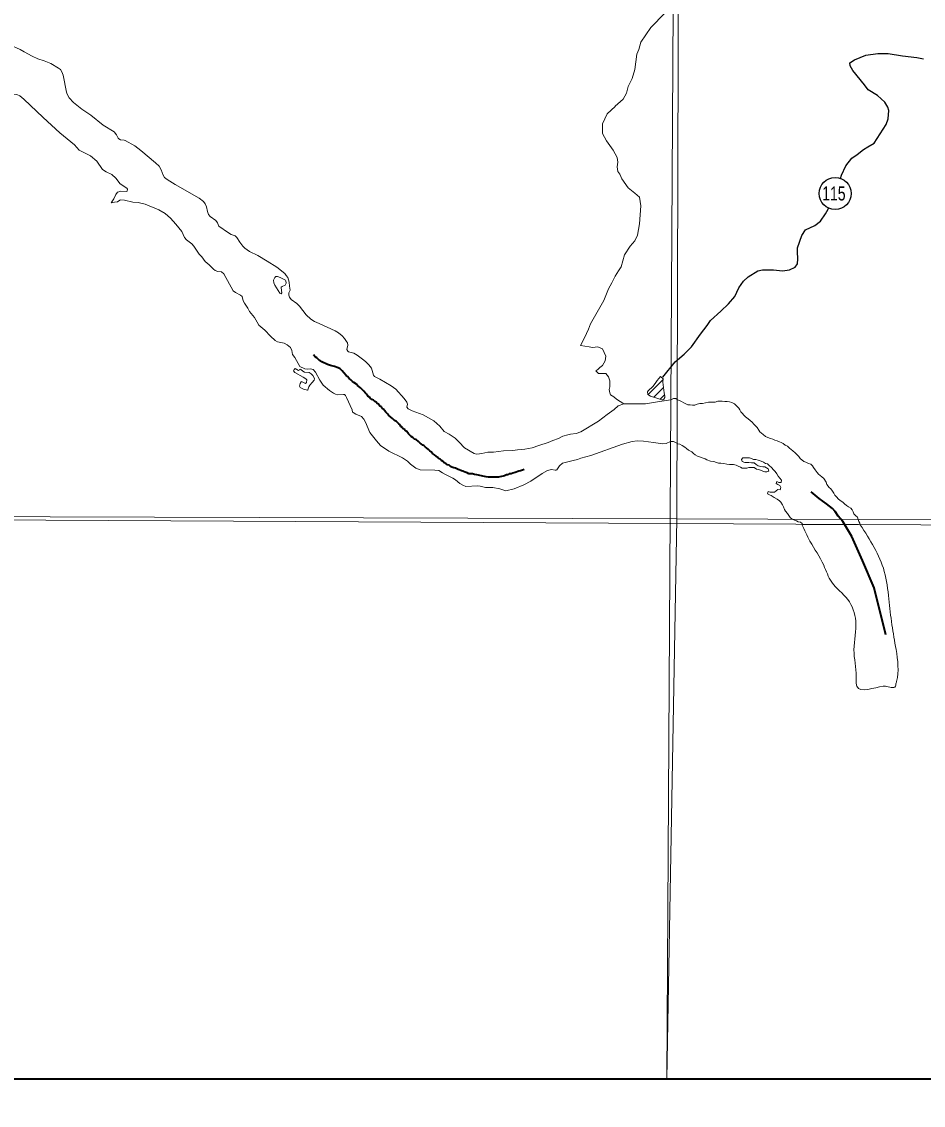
# Model space of a CAD drawing. Extents: x -1643653 to 4543381, y 1624270 to 13878484.
# Drawn here: x 604258 to 608778, y 8895895 to 8901328 of the extents above; entities that cross this region are included whole.
import ezdxf
from ezdxf.enums import TextEntityAlignment as Align

# ---------------------------------------------------------------- set-up
doc = ezdxf.new("R2010")
doc.units = 0
doc.header["$LTSCALE"] = 200
doc.linetypes.add('LONG_DASH_SHORT_DASH', pattern=[9.9, 6, -1.2, 1.5, -1.2])
doc.layers.add('6', color=7, linetype='Continuous', lineweight=13)
doc.layers.add('60', color=7, linetype='Continuous', lineweight=13)

msp = doc.modelspace()

# ---------------------------------------------------------------- linework, layer by layer
at = {"layer": '6'}
for p, q in [((607398.2, 8899458.9), (607473.3, 8899534)), ((607427.1, 8899445.4), (607476, 8899494.2)), ((607458.9, 8899434.7), (607481.1, 8899456.9)), ((608462.4, 8898805.8), (608169.4, 8898807.8))]:
    msp.add_line(p, q, dxfattribs=at)
at = {"layer": '6', "lineweight": 35}
msp.add_lwpolyline([(574695.3, 8924769.6), (626625.7, 8924769.6), (626625.7, 8896026.7), (574695.3, 8896026.7)], close=True, dxfattribs=at)
at = {"layer": '6'}
for points in [[(607657.7, 8924743.3), (607574.2, 8909874.9), (607492.3, 8896026.7)], [(607518.6, 8901403.9), (607482.1, 8901370.7), (607412.3, 8901297.6), (607362.4, 8901224.5), (607352.5, 8901188), (607342.5, 8901164.7), (607332.5, 8901088.4), (607319.2, 8901041.9), (607299.3, 8901002), (607289.3, 8900968.8), (607272.7, 8900938.9), (607233.9, 8900903.3)], [(603607.9, 8901202.5), (603628.6, 8901215.9), (603671.7, 8901230.7), (603774.9, 8901247.2), (603862.9, 8901251.2), (603892.8, 8901248.7), (603993.8, 8901227), (604022.6, 8901225.8), (604073.7, 8901229.1), (604097.1, 8901225.2), (604136.5, 8901210.6), (604149.3, 8901209.6), (604198.3, 8901211), (604250.4, 8901188.4), (604270.6, 8901176.9)], [(604270.6, 8901176.9), (604309.9, 8901154.5), (604339.3, 8901141.9), (604370.9, 8901131.4)], [(604370.9, 8901131.4), (604370.9, 8901131.4), (604403.6, 8901117.1), (604442.5, 8901095.2), (604452, 8901087.1), (604458.6, 8901076.9), (604465.4, 8901060), (604482, 8900973.9), (604485.2, 8900964.1), (604495.8, 8900945.5), (604517.3, 8900922.7), (604558.5, 8900888.9), (604603.8, 8900858.4), (604667, 8900809.4), (604720.7, 8900774.8), (604733.1, 8900760.8), (604741.5, 8900744.4), (604745.2, 8900740.3), (604753.2, 8900735.9), (604770.9, 8900734.2), (604776.8, 8900732.2), (604824.3, 8900704.6), (604854.7, 8900681.5), (604929.1, 8900620.1), (604947.7, 8900602.6), (604957.6, 8900585), (604966.3, 8900557.4), (604974.2, 8900547), (604987.4, 8900535.9), (605027.8, 8900510.6), (605147.2, 8900442.4), (605169.2, 8900426.4), (605178, 8900414.5), (605184.6, 8900400), (605189.5, 8900375.3), (605194.2, 8900361.7), (605203.3, 8900351.7), (605231.7, 8900331.2), (605239.8, 8900319.8), (605246.1, 8900303.3), (605294.8, 8900269.1), (605308.7, 8900261.3), (605318.4, 8900257.2)], [(604366, 8900847), (604269.1, 8900939.9), (604248, 8900956), (604232.7, 8900962.7), (604218.8, 8900964.1), (604182.6, 8900956.3), (604161.8, 8900955.6), (604125.6, 8900973.4), (604104.3, 8900978.3), (604083.2, 8900978.5), (604062.8, 8900972.3)], [(607232.8, 8900902.4), (607193, 8900865.8), (607169.7, 8900816), (607169.7, 8900766.2), (607189.6, 8900729.7), (607222.9, 8900683.2), (607242.8, 8900646.7), (607246.1, 8900623.4), (607242.8, 8900600.2), (607246.1, 8900576.9), (607256.1, 8900563.6), (607266.1, 8900540.4), (607299.3, 8900493.9), (607332.5, 8900467.3), (607355.8, 8900447.4), (607362.4, 8900404.2), (607355.8, 8900314.6), (607345.8, 8900258.1), (607332.5, 8900228.2), (607309.3, 8900201.6), (607279.4, 8900158.5), (607262.7, 8900098.7), (607249.5, 8900078.8), (607232.8, 8900052.2), (607216.2, 8900019), (607199.6, 8899989.1), (607176.3, 8899929.3), (607109.9, 8899813.1), (607099.9, 8899786.5), (607080, 8899743.3), (607060, 8899703.5), (607103.2, 8899696.8), (607119.8, 8899693.5), (607146.4, 8899696.8), (607169.7, 8899686.9), (607186.3, 8899650.3), (607183, 8899627.1), (607169.7, 8899603.8), (607156.4, 8899593.9), (607146.4, 8899583.9), (607136.5, 8899577.3), (607149.8, 8899564), (607186.3, 8899564), (607199.6, 8899547.4), (607206.2, 8899527.4), (607206.2, 8899507.5), (607206.2, 8899497.6), (607202.9, 8899484.3), (607206.2, 8899467.7), (607209.6, 8899457.7), (607226.2, 8899447.8), (607239.5, 8899434.5), (607276, 8899411.2)], [(604545.7, 8900683.2), (604522.7, 8900710.9), (604449.6, 8900771.1), (604366, 8900847)], [(604745.3, 8900474.6), (604755.6, 8900477.1), (604782.2, 8900475.7), (604787.1, 8900478.4), (604787.9, 8900487.3), (604784.5, 8900492.2), (604752, 8900515.1), (604729.6, 8900542.8), (604709.4, 8900561), (604681.6, 8900575), (604663.6, 8900587.3), (604633.8, 8900627.5), (604602, 8900655.7), (604545.7, 8900683.2)], [(604706.6, 8900419.8), (604719.1, 8900439.6), (604727.3, 8900457.6), (604729.9, 8900461.2), (604729.9, 8900461.2)], [(604729.9, 8900461.2), (604737.9, 8900472.8), (604745.3, 8900474.6)], [(605045.3, 8900294.2), (605031, 8900312.3), (605003.2, 8900342.6), (604977.4, 8900365.2), (604945.5, 8900383.7), (604877.4, 8900413.4), (604842.3, 8900421.4), (604815.8, 8900423.5), (604773.8, 8900433.3), (604754.4, 8900435.3), (604749.3, 8900433), (604738.7, 8900423.7), (604723, 8900423.6), (604706.6, 8900419.8)], [(605438.8, 8899820.5), (605424.5, 8899844.7), (605400.3, 8899874.5), (605391.9, 8899891.1), (605374.3, 8899916.5), (605368.7, 8899929), (605362.7, 8899950.1), (605355.1, 8899957.3), (605329.3, 8899970.5), (605318.8, 8899978.5), (605271.5, 8900063.6), (605260.1, 8900073.8), (605241.3, 8900075.8), (605228.1, 8900080.5), (605218.7, 8900087.6), (605197.7, 8900109.2), (605177.8, 8900125.6), (605161.6, 8900148.5), (605147.3, 8900162.1), (605121.1, 8900202.5), (605110.9, 8900213.2), (605084.9, 8900233.7), (605074.1, 8900246.2), (605060.1, 8900275.4), (605045.3, 8900294.2)], [(605318.4, 8900257.2), (605328.1, 8900253.2), (605335.8, 8900246.2), (605350.9, 8900222.8), (605366.1, 8900202.7), (605377.3, 8900192.3), (605399.9, 8900175.6), (605442.3, 8900156.2), (605489.3, 8900126.6)], [(605489.3, 8900126.6), (605536.4, 8900097), (605576.3, 8900065.9), (605584, 8900055.8)], [(605584, 8900055.8), (605591.8, 8900045.6), (605599.5, 8900021.8), (605601.3, 8900001.9)], [(605601.3, 8900001.9), (605603.1, 8899982.1), (605597.9, 8899967.5), (605596.6, 8899957), (605600.2, 8899946.1), (605609.6, 8899935.7), (605637, 8899914.4), (605637, 8899914.4), (605649.8, 8899902), (605684.5, 8899857.5), (605707.9, 8899837.1), (605725.2, 8899825.1), (605748.8, 8899814.5)], [(605651.9, 8899599.2), (605627.2, 8899644.2), (605614.9, 8899659.3), (605613, 8899680), (605604.8, 8899694.2), (605588.8, 8899707.8), (605573.8, 8899716.3), (605540.9, 8899723.1), (605528.7, 8899729.8), (605504.9, 8899751.3), (605476.1, 8899781.6), (605446.9, 8899806.9), (605438.8, 8899820.5)], [(605748.8, 8899814.5), (605828.9, 8899778.6), (605845.6, 8899768.4), (605864.6, 8899753.2), (605875.9, 8899739.1)], [(605875.9, 8899739.1), (605887.1, 8899725), (605890.8, 8899718.1), (605893.6, 8899706.3), (605887.9, 8899684.9), (605892.5, 8899676.5), (605897.1, 8899672.9), (605922.3, 8899665.2), (605940.2, 8899656.1), (605972.7, 8899630.7), (605982.6, 8899621.7)], [(605800.4, 8899478.3), (605768.7, 8899506.2), (605752.1, 8899530.8), (605730.5, 8899570.1), (605719.2, 8899583.9), (605706, 8899587.4), (605690.9, 8899586.3), (605677.8, 8899587.4), (605651.9, 8899599.2)], [(605982.6, 8899621.7), (605997.9, 8899607.7), (606011.1, 8899590.2), (606021.8, 8899555.1), (606026.3, 8899548.7), (606053.9, 8899535.2), (606082.6, 8899518.2)], [(605886.8, 8899444.2), (605880.5, 8899454.1), (605875.6, 8899458), (605871.8, 8899459), (605843.6, 8899457.8), (605831.8, 8899459.6), (605821.4, 8899464.6), (605800.4, 8899478.3)], [(606082.6, 8899518.2), (606110.4, 8899501.7), (606133.8, 8899485.1), (606175, 8899438.1), (606188.2, 8899420.1), (606191.5, 8899410.3), (606189.5, 8899394.8), (606194.9, 8899386.7), (606215.6, 8899376.8), (606270.9, 8899356.2), (606324.1, 8899326.3), (606339, 8899313.3)], [(606167, 8899141.3), (606097.8, 8899173.8), (606057.4, 8899203.2), (606036.3, 8899225.7), (606003.4, 8899268.5), (605982, 8899319.3), (605972.7, 8899335.8), (605960.9, 8899348.2), (605932.8, 8899360.8), (605920.3, 8899368.7), (605916, 8899369.4), (605914.2, 8899381.2), (605886.8, 8899444.2)], [(606996.3, 8899256.7), (607009.1, 8899260.5), (607037.2, 8899263), (607061.2, 8899271.7), (607150.5, 8899324.7), (607193.7, 8899358.8), (607228.5, 8899383), (607248.7, 8899401.6), (607276, 8899411.2), (607305.9, 8899411.2), (607385.7, 8899411.2), (607445.5, 8899421.2), (607512.3, 8899432.5)], [(607512.3, 8899432.5), (607525.9, 8899438.3), (607537.1, 8899438.2), (607545.2, 8899432.1), (607555.3, 8899427.9), (607565.5, 8899422.8), (607577.6, 8899416.6), (607586.8, 8899411.4), (607597.9, 8899407.3), (607609.1, 8899406.2), (607621.3, 8899405.1), (607633.5, 8899406), (607643.7, 8899410), (607658, 8899413), (607671.2, 8899413.9), (607701.8, 8899420.9), (607713, 8899420.8), (607723.1, 8899420.7), (607734.3, 8899420.7), (607747.6, 8899424.6), (607757.7, 8899424.6), (607770, 8899424.5), (607783.2, 8899424.4), (607795.4, 8899424.3), (607806.6, 8899422.2), (607817.7, 8899418.1), (607830.9, 8899411.9), (607838, 8899404.7), (607846.1, 8899397.5), (607853.1, 8899390.3)], [(607853.1, 8899390.3), (607858.2, 8899381.2), (607863.2, 8899371.9), (607871.3, 8899363.7), (607878.3, 8899355.6), (607887.4, 8899347.3), (607899.6, 8899336.1), (607919.8, 8899319.6), (607927.8, 8899309.4), (607937, 8899302.2), (607946, 8899293), (607954.1, 8899280.7), (607959.1, 8899271.5), (607975.3, 8899258.1), (607987.4, 8899247.9), (607998.6, 8899242.7), (608011.8, 8899238.6), (608023, 8899235.4), (608033.1, 8899230.3), (608045.3, 8899226.1), (608056.4, 8899222), (608065.6, 8899217.8), (608075.7, 8899212.7), (608085.8, 8899205.5), (608097, 8899199.3), (608108.1, 8899190.1), (608116.2, 8899182.9), (608124.3, 8899176.7), (608135.4, 8899166.4), (608142.5, 8899159.3), (608154.6, 8899148), (608160.6, 8899137.8), (608178.8, 8899123.4), (608189, 8899119.2), (608202.2, 8899112), (608214.3, 8899108.9), (608222.4, 8899101.7), (608228.5, 8899092.5), (608236.5, 8899081.2), (608246.6, 8899067.9), (608252.7, 8899058.7), (608260.8, 8899052.6), (608269.9, 8899046.4), (608279, 8899038.2), (608291, 8899018.7), (608295, 8899007.5), (608306.1, 8898992.2), (608314.2, 8898985), (608322.3, 8898973.7), (608329.3, 8898963.5), (608335.3, 8898953.3), (608342.4, 8898945.1), (608352.5, 8898933.8), (608365.7, 8898923.5), (608374.8, 8898918.4), (608383.9, 8898910.2), (608393, 8898903), (608403.1, 8898895.8), (608414.2, 8898889.6), (608421.3, 8898880.4), (608427.3, 8898870.2), (608430.3, 8898859.9), (608439.4, 8898850.7), (608447.5, 8898843.5), (608451.5, 8898832.3)], [(606339, 8899313.3), (606353.8, 8899300.2), (606375.8, 8899273.6), (606401.3, 8899259.5), (606425.6, 8899243.5), (606430.3, 8899239.2)], [(606430.3, 8899239.2), (606451.1, 8899220.5), (606477.9, 8899191.6), (606526.1, 8899162.9), (606538.8, 8899160.4), (606552.3, 8899160.9), (606564.8, 8899163.4)], [(606850.9, 8899202.7), (606897.3, 8899217.3), (606921.3, 8899228.2), (606948.9, 8899237.7), (606970.8, 8899249.3), (606996.3, 8899256.7)], [(607510.3, 8899223.4), (607489.5, 8899213.8), (607472.3, 8899210.6), (607425.7, 8899218.6), (607376, 8899224.9), (607343.2, 8899226.9), (607318.7, 8899223.8), (607269.6, 8899209.6), (607112, 8899153.1), (607061.6, 8899139.4), (607044.9, 8899132.1), (607038.2, 8899131.2)], [(607965.2, 8899123.7), (607951, 8899129.9), (607937.8, 8899133.1), (607926.6, 8899133.2), (607916.5, 8899137.3), (607906.3, 8899140.4), (607892.1, 8899140.5), (607872.8, 8899140.6), (607866.6, 8899132.5), (607870.6, 8899122.3), (607882.8, 8899117.1), (607894, 8899117.1), (607904.2, 8899117), (607917.4, 8899116.9), (607930.6, 8899115.8), (607940.7, 8899107.6), (607950.8, 8899101.4), (607963, 8899097.3), (607974.2, 8899096.2), (607984.4, 8899096.1), (607999.6, 8899085.8), (608003.5, 8899073.6), (607993.3, 8899070.6), (607983.2, 8899070.6), (607973, 8899074.8), (607961.9, 8899078.9), (607952.7, 8899083.1), (607941.6, 8899084.2), (607930.4, 8899092.4), (607917.2, 8899093.5), (607903, 8899092.6), (607892.8, 8899089.6), (607881.6, 8899088.6), (607870.4, 8899088.7), (607861.3, 8899093.8), (607850.1, 8899100), (607840, 8899104.2), (607826.8, 8899108.3), (607816.6, 8899108.4), (607806.4, 8899108.4), (607793.2, 8899109.6), (607778, 8899112.7), (607763.7, 8899113.8), (607751.5, 8899113.9), (607741.4, 8899118), (607727.2, 8899122.2), (607712, 8899125.3), (607693.7, 8899131.6), (607684.6, 8899136.7), (607674.4, 8899139.9), (607661.2, 8899144), (607646, 8899150.2), (607634.8, 8899155.4), (607625.7, 8899163.6), (607617.7, 8899170.8), (607600.4, 8899180.1), (607591.3, 8899188.3), (607583.2, 8899194.4), (607569.1, 8899203.7), (607557.9, 8899208.9), (607547.8, 8899212), (607536.6, 8899218.2), (607525.4, 8899222.3), (607515.3, 8899222.4), (607510.3, 8899223.4)], [(606564.8, 8899163.4), (606594.8, 8899169.2), (606624, 8899170.2), (606673, 8899176.3), (606719.7, 8899178.1), (606743.5, 8899180.8)], [(606743.5, 8899180.8), (606780.2, 8899185.1), (606817.4, 8899192.1), (606850.9, 8899202.7)], [(606368.4, 8899065.7), (606348.9, 8899077), (606329, 8899080.2), (606255.6, 8899080.9), (606233.8, 8899088.8), (606207, 8899108.8), (606191.6, 8899125.1), (606167, 8899141.3)], [(607038.2, 8899131.2), (607030.1, 8899130.2), (606968.5, 8899113.9), (606953.5, 8899101.6), (606940.8, 8899080.5), (606936.9, 8899079.8)], [(608076.6, 8898895.8), (608072.6, 8898905), (608064.5, 8898918.3), (608056.4, 8898925.5), (608045.3, 8898934.7), (608031.1, 8898943), (608015.9, 8898952.2), (608006.8, 8898956.4), (607996.7, 8898961.5), (607999.8, 8898971.7), (608011, 8898968.6), (608022.1, 8898968.5), (608032.3, 8898969.5), (608040.5, 8898976.5), (608048.7, 8898982.6), (608060.9, 8898981.5), (608064, 8898992.7), (608059, 8899001.9), (608048.8, 8899007.1), (608039.7, 8899013.2), (608043.9, 8899022.4), (608054, 8899017.2), (608066.2, 8899017.1), (608067.3, 8899029.3), (608059.2, 8899038.6), (608051.2, 8899049.8), (608044.1, 8899061.1), (608036.1, 8899072.3), (608027, 8899080.5), (608017.9, 8899092.8), (608005.8, 8899102.1), (607997.7, 8899110.3), (607987.5, 8899113.4), (607977.4, 8899119.6), (607965.2, 8899123.7)], [(606669.7, 8898980.5), (606654.6, 8898985.8), (606620, 8898992.5), (606583.1, 8898992.2), (606556.5, 8898999.1), (606542.7, 8899000.4), (606485.3, 8898997.2), (606468.8, 8899003.8), (606455.3, 8899011.8), (606432, 8899031.1), (606419.7, 8899039.2), (606382.7, 8899057.4), (606368.4, 8899065.7)], [(606936.9, 8899079.8), (606931.9, 8899079.1), (606913.4, 8899083.4), (606894.4, 8899077.1), (606866.6, 8899063), (606810.7, 8899023.7), (606776, 8899005.8), (606726.3, 8898985.3), (606684.8, 8898975.2), (606669.7, 8898980.5)], [(574695.3, 8898953.2), (596544.3, 8898870.4), (626625.7, 8898710.8)], [(608169.4, 8898807.8), (608170.6, 8898811.7), (608162.5, 8898818.9), (608151.3, 8898821), (608142.2, 8898825.1), (608132.1, 8898829.2), (608120.9, 8898833.4), (608110.8, 8898841.6), (608104.8, 8898852.9), (608096.7, 8898862.1), (608087.6, 8898873.3), (608081.6, 8898882.6), (608076.6, 8898895.8)], [(608451.5, 8898832.3), (608454.5, 8898822.1), (608460.5, 8898813.9), (608462.4, 8898805.8), (608169.4, 8898807.8)]]:
    msp.add_lwpolyline(points, dxfattribs=at)
for points in [[(618535.2, 8909853.3), (607574.3, 8909890.7), (607543.3, 8898835.3), (618504.2, 8898795.8)], [(605578, 8900006.4), (605581.1, 8900009.7), (605583.1, 8900017.2), (605581.8, 8900027.9), (605579.6, 8900031.9), (605553.8, 8900045.2), (605540.6, 8900049.4), (605532.2, 8900049.6), (605526.5, 8900045.7), (605520.9, 8900031.3), (605522.3, 8900018.3), (605527.3, 8900006.6), (605552.8, 8899966.1), (605559, 8899963.9), (605562.7, 8899968.7), (605558.6, 8899992.7), (605559.4, 8899996.8), (605563.9, 8900000.6)], [(605726.5, 8899537.9), (605724, 8899530.6), (605714.4, 8899518.2), (605703, 8899506.1), (605697.8, 8899496.6), (605691.8, 8899481.5), (605690, 8899479.8), (605670.7, 8899486.1), (605654.2, 8899494.3), (605651.4, 8899501.1), (605654.2, 8899514.3), (605658.7, 8899522.5), (605659.8, 8899523), (605664.4, 8899521.9), (605680, 8899513.5), (605686.4, 8899518), (605687.1, 8899532.4), (605682.6, 8899537.5), (605669, 8899546.2), (605627.1, 8899569.7), (605621, 8899577.3), (605624.1, 8899584.8), (605629.5, 8899588.5), (605644.9, 8899579.4), (605648.7, 8899580.6), (605650.3, 8899583.7), (605653.3, 8899585.6), (605658.1, 8899583.4), (605667.7, 8899575.2), (605676.3, 8899570.6), (605698.8, 8899568.8), (605709.7, 8899562.8), (605717.5, 8899553.2), (605726.3, 8899538.9)], [(607460.5, 8899548.4), (607473.4, 8899537.4), (607473.1, 8899520.7), (607479, 8899466.9), (607482.5, 8899450.2), (607481.5, 8899443.7), (607477.8, 8899435.1), (607475, 8899432.4), (607467.5, 8899432.5), (607456.8, 8899435.3), (607411.1, 8899450.8), (607397.8, 8899459.1), (607396.2, 8899472.7), (607398.9, 8899476.5), (607421.7, 8899498.1), (607434.4, 8899514.6), (607443.2, 8899529)], [(596544.3, 8898870.4), (596531.7, 8896026.7), (607492.3, 8896026.7), (607543.3, 8898835.3)]]:
    msp.add_lwpolyline(points, close=True, dxfattribs=at)
at = {"layer": '6', "lineweight": 25}
for points in [[(608362.5, 8900541.9), (608368.2, 8900558.4), (608389.8, 8900605.2), (608420.5, 8900642.9), (608446, 8900662.2), (608477.7, 8900686.6), (608500.2, 8900699.8), (608531.8, 8900719.1), (608592.3, 8900811.7), (608601.6, 8900840.2), (608604.8, 8900883), (608599.7, 8900899.3), (608584.6, 8900924.8), (608548, 8900957.4), (608502.2, 8900986.1), (608484, 8901011.6), (608424.2, 8901083), (608411, 8901106.4), (608410, 8901120.7), (608433.5, 8901137), (608490.7, 8901160.3), (608550.8, 8901168.3), (608602.8, 8901168.2), (608674, 8901155.9), (608745.3, 8901147.6), (608778.9, 8901141.4)], [(607472.2, 8899545.8), (607534.4, 8899621.6), (607579.4, 8899661.2), (607616.2, 8899696.8), (607661.2, 8899761.9), (607694, 8899804.7), (607711.4, 8899829.1), (607763.6, 8899875.9), (607801.4, 8899912.5), (607833.1, 8899950.1), (607852.6, 8899993.9), (607877.2, 8900026.4), (607900.7, 8900048.8), (607948.7, 8900079.3), (607972.2, 8900084.3), (608027.2, 8900083.2), (608072, 8900078.1), (608106.7, 8900084.1), (608135.2, 8900096.3), (608147.5, 8900113.6), (608148.6, 8900139), (608146.7, 8900173.7), (608147.8, 8900194.1), (608168.4, 8900255.2), (608186.9, 8900283.6), (608234.8, 8900306), (608263.4, 8900327.3), (608288, 8900363.9), (608301.4, 8900388.4), (608303.7, 8900393.1)]]:
    msp.add_lwpolyline(points, dxfattribs=at)
at = {"layer": '6', "linetype": 'LONG_DASH_SHORT_DASH', "lineweight": 35}
for points in [[(605956.8, 8899491.3), (605948.6, 8899499.4), (605941.5, 8899504.1), (605935.9, 8899511.2), (605923.7, 8899519.4), (605916, 8899524), (605907.9, 8899532.7), (605899.8, 8899538.3), (605891.6, 8899548.5), (605884.5, 8899554.7), (605873.3, 8899567.4), (605865.1, 8899577.7), (605855, 8899586.9), (605844.3, 8899592), (605825.4, 8899599.7), (605805.6, 8899603.2), (605791.3, 8899609.4), (605781.7, 8899613.5), (605773, 8899617.5), (605763.3, 8899621.6), (605758.2, 8899625.7), (605751.6, 8899628.8), (605744.5, 8899635.4), (605736.9, 8899643.1), (605728.7, 8899648.2), (605721.2, 8899657.3)], [(606202.1, 8899256.6), (606197.1, 8899261.7), (606188.4, 8899272.5), (606181.8, 8899277.1), (606178.2, 8899283.7), (606171.1, 8899287.3), (606167, 8899293.9), (606159.4, 8899298), (606155.3, 8899306.2), (606148.2, 8899311.3), (606137, 8899323.6), (606127.3, 8899328.2), (606117.1, 8899337.9), (606108, 8899345.6), (606097.3, 8899355.8), (606091.2, 8899361.4), (606084, 8899370.1), (606076.9, 8899377.8), (606072.3, 8899385.4), (606065.2, 8899389.5), (606061.1, 8899397.2), (606054, 8899400.8), (606046.9, 8899410.5), (606039.7, 8899414.1), (606035.2, 8899420.2), (606028, 8899423.8), (606020.9, 8899430.4), (606013.8, 8899434), (606005.6, 8899440.7), (606001.1, 8899444.8), (605993.4, 8899450.9), (605985.8, 8899460.1), (605980.7, 8899465.7), (605973.1, 8899474.9), (605968.5, 8899480), (605961.3, 8899486.7), (605956.8, 8899491.3)], [(606696.3, 8899056.2), (606688.7, 8899055.7), (606679.1, 8899051.6), (606671.4, 8899049.1), (606662.8, 8899047.5), (606654.6, 8899046), (606649, 8899045), (606641.9, 8899044), (606630.2, 8899044), (606622.6, 8899044), (606614.4, 8899044), (606609.8, 8899044), (606602.2, 8899044.5), (606596.6, 8899045), (606586.9, 8899046.5), (606578.3, 8899048.1), (606570.1, 8899049.6), (606562.5, 8899051.1), (606554.9, 8899052.7), (606548.3, 8899054.2), (606540.1, 8899055.7), (606528.4, 8899057.2), (606517.7, 8899060.3), (606508.1, 8899061.8), (606498.9, 8899061.8), (606490.8, 8899065.9), (606481.1, 8899069.5), (606472.9, 8899072.6), (606468.9, 8899073.6), (606462.8, 8899076.7), (606458.7, 8899077.7), (606451.1, 8899081.3), (606446.5, 8899082.3), (606439.8, 8899086.4), (606432.2, 8899090), (606423.6, 8899090.5), (606414.4, 8899094.1), (606408.3, 8899097.6), (606400.7, 8899103.8), (606392.5, 8899106.8), (606384.4, 8899113.5), (606375.7, 8899116.6), (606370.1, 8899122.7), (606362.5, 8899127.8), (606355.4, 8899133.9), (606347.7, 8899138), (606342.6, 8899144.7), (606336, 8899148.8), (606326.8, 8899156.9), (606316.7, 8899162.6), (606311.6, 8899171.8), (606304, 8899176.4), (606297.3, 8899183.5), (606288.2, 8899190.7), (606281.6, 8899194.8), (606273.4, 8899202.4), (606268.3, 8899205.5), (606260.2, 8899212.2), (606255.6, 8899215.2), (606248, 8899222.9), (606236.2, 8899232.6), (606227.6, 8899235.2), (606219.4, 8899243.3), (606211.3, 8899247.4), (606202.1, 8899256.6)], [(606776.9, 8899082.3), (606776.7, 8899082.3), (606768.6, 8899079.2), (606759.4, 8899076.2), (606750.8, 8899073.6), (606731.5, 8899067.5), (606720.8, 8899063.9), (606711.6, 8899061.3), (606701.9, 8899060.3), (606696.3, 8899056.2)], [(608589.7, 8898253.2), (608531.8, 8898489.6), (608473.8, 8898626.9), (608419.7, 8898746.8), (608375.2, 8898822.2), (608352, 8898849.2), (608336.5, 8898872.3), (608323.3, 8898886.6), (608292.9, 8898910.1), (608256.3, 8898937.7), (608216.7, 8898970.6)]]:
    msp.add_lwpolyline(points, dxfattribs=at)
at = {"layer": '6', "lineweight": 25}
msp.add_circle((608336.3, 8900466.1), 80.3, dxfattribs=at)
at = {"layer": '6'}
msp.add_spline([(608169.4, 8898807.8), (608210, 8898723.6), (608278.8, 8898603.2), (608318.9, 8898517.3), (608399.1, 8898431.3), (608439.2, 8898322.4), (608430.6, 8898179.2), (608442.1, 8898044.5), (608442.1, 8898015.4), (608445, 8897995.8), (608576.8, 8897995.8), (608588.2, 8897995.8), (608638.5, 8897995.8), (608640.5, 8898005.2), (608644.2, 8898020.1), (608641.5, 8898180.1), (608620.8, 8898304.5), (608605.4, 8898434.2), (608582.5, 8898571.7), (608462.4, 8898805.8)], degree=3, dxfattribs=at)
at = {"layer": '60', "lineweight": 25}
msp.add_spline([(814781, 9009175.5), (814787.2, 9009173.4), (814796.9, 9009173.4), (814799.4, 9009172.4), (814805.1, 9009174.5), (814805.6, 9009176.5), (814811.7, 9009179.5), (814811.7, 9009179.5), (814801.5, 9009181), (814790.7, 9009181.5), (814784.1, 9009183.1), (814777.4, 9009185.1), (814778.4, 9009175.5)], degree=3, dxfattribs=at)

# ---------------------------------------------------------------- texts
at = {"layer": '6', "width": 0.75}
msp.add_text('115', height=70, dxfattribs=at).set_placement((608329.9, 8900431.4), align=Align.CENTER)

doc.saveas('drawing.dxf')
